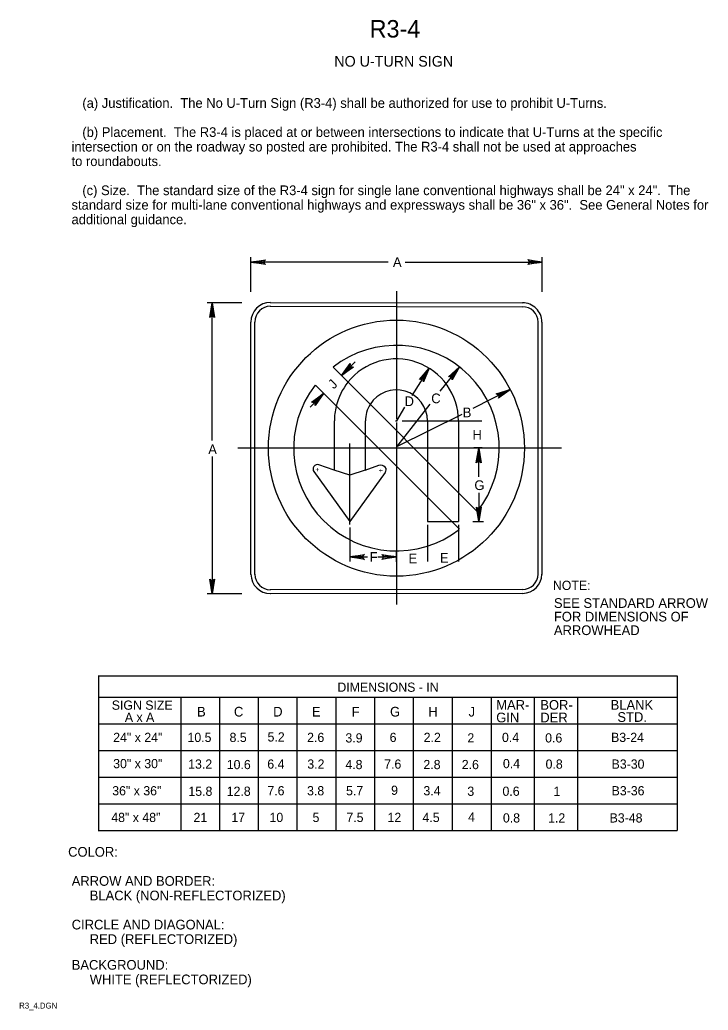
# Model space of a CAD drawing. Extents: x 0.013 to 0.19, y 0.004 to 0.259.
import ezdxf

# ---------------------------------------------------------------- set-up
doc = ezdxf.new("R2010")
doc.units = 0
for name, color, linetype in [('1', 7, 'Continuous'), ('2', 7, 'Continuous'), ('3', 7, 'Continuous')]:
    doc.layers.add(name, color=color, linetype=linetype)

# ---------------------------------------------------------------- blocks, each defined once
blk = doc.blocks.new('RARROW')
at = {"layer": '3'}
for p, q in [((-2.156, 0.28500000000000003), (-2.2665, 0.384625)), ((-2.2665, 0.384625), (0, 0)), ((0, 0), (-2.2665, -0.379125)), ((-2.156, 0.28500000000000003), (-2.075625, 0.12075)), ((0, 0), (-2.156, 0.28500000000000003)), ((-2.14975, -0.2705), (0, 0)), ((-2.075625, 0.12075), (0, 0)), ((0, 0), (-2.074, -0.108)), ((-2.2665, -0.379125), (-2.14975, -0.2705)), ((-2.074, -0.108), (-2.14975, -0.2705))]:
    blk.add_line(p, q, dxfattribs=at)

msp = doc.modelspace()

# ---------------------------------------------------------------- linework, layer by layer
at = {"layer": '1'}
for p, q in [((0.10975, 0.18925), (0.10975, 0.15637500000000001)), ((0.0935, 0.169625), (0.130625, 0.1325)), ((0.088875, 0.165), (0.126, 0.12787500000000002)), ((0.10975, 0.156125), (0.10975, 0.155625)), ((0.11775000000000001, 0.155875), (0.11775000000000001, 0.145375)), ((0.12575, 0.155875), (0.12575, 0.137375)), ((0.10975, 0.155375), (0.10975, 0.1085)), ((0.11775000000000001, 0.145375), (0.11775000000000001, 0.136125)), ((0.11775000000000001, 0.136125), (0.11775000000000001, 0.129875)), ((0.12575, 0.137375), (0.12575, 0.129875))]:
    msp.add_line(p, q, dxfattribs=at)
at = {"layer": '3'}
for p, q in [((0.07225, 0.189090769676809), (0.07225, 0.198)), ((0.107625, 0.19675), (0.07225, 0.19675)), ((0.112, 0.19675), (0.147375, 0.19675)), ((0.147375, 0.189090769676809), (0.147375, 0.198)), ((0.07725, 0.186375), (0.14225000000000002, 0.18625)), ((0.06990747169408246, 0.18625), (0.061, 0.18625)), ((0.06225, 0.15075), (0.06225, 0.18625)), ((0.07725, 0.185375), (0.14225000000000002, 0.18525)), ((0.07225, 0.11625), (0.07225, 0.18125)), ((0.07325, 0.11625), (0.07325, 0.18125)), ((0.14625, 0.18125), (0.14625, 0.11625)), ((0.14725, 0.18125), (0.14725, 0.11625)), ((0.099125, 0.171), (0.095625, 0.1675)), ((0.11825000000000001, 0.169375), (0.11375, 0.162375)), ((0.126, 0.16975), (0.121, 0.1635)), ((0.139125, 0.163875), (0.1295, 0.159)), ((0.08750000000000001, 0.15937500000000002), (0.091, 0.162875)), ((0.11837500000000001, 0.160125), (0.10975, 0.149125)), ((0.111875, 0.15937500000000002), (0.10975, 0.155875)), ((0.09375, 0.155875), (0.09375, 0.143125)), ((0.10175000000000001, 0.155875), (0.10175000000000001, 0.152125)), ((0.1095, 0.155875), (0.11, 0.155875)), ((0.12662500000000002, 0.1575), (0.10975, 0.149125)), ((0.11125, 0.155875), (0.13175, 0.155875)), ((0.10175000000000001, 0.152125), (0.10175000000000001, 0.143125)), ((0.068875, 0.148875), (0.152375, 0.148875)), ((0.09775, 0.129125), (0.09775, 0.15)), ((0.131875, 0.148875), (0.12975, 0.148875)), ((0.131, 0.141375), (0.131, 0.148875)), ((0.131, 0.143875), (0.131, 0.148875)), ((0.06225, 0.146625), (0.06225, 0.11125)), ((0.09375, 0.143125), (0.08975, 0.1445)), ((0.09775, 0.141875), (0.09375, 0.143125)), ((0.10175000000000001, 0.143125), (0.09775, 0.141875)), ((0.10175000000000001, 0.143125), (0.10525, 0.144375)), ((0.0885, 0.14275000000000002), (0.09775, 0.129875)), ((0.106875, 0.14250000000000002), (0.09775, 0.129875)), ((0.106875, 0.14250000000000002), (0.106875, 0.14250000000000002)), ((0.131, 0.13725), (0.131, 0.129875)), ((0.09775, 0.128375), (0.09775, 0.11962500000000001)), ((0.11775000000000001, 0.129875), (0.124, 0.129875)), ((0.11775000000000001, 0.129), (0.11775000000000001, 0.11962500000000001)), ((0.124, 0.129875), (0.12575, 0.129875)), ((0.12575, 0.129), (0.12575, 0.11962500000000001)), ((0.1295, 0.129875), (0.13225, 0.129875)), ((0.09775, 0.12075), (0.1023042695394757, 0.12075)), ((0.105, 0.12075), (0.10975, 0.12075)), ((0.10975, 0.11950000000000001), (0.10975, 0.122125)), ((0.14225000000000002, 0.112375), (0.07725, 0.11225)), ((0.06990747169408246, 0.11125), (0.061, 0.11125)), ((0.14225000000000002, 0.111375), (0.07725, 0.11125)), ((0.032875, 0.090125), (0.182125, 0.090125)), ((0.032916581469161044, 0.09012213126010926), (0.032916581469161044, 0.050247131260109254)), ((0.18216658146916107, 0.09012213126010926), (0.18216658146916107, 0.050247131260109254)), ((0.182125, 0.0845), (0.032875, 0.0845)), ((0.05416658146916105, 0.08449713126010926), (0.05416658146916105, 0.050247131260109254)), ((0.064125, 0.0845), (0.064125, 0.05025)), ((0.074125, 0.0845), (0.074125, 0.05025)), ((0.084125, 0.0845), (0.084125, 0.05025)), ((0.094125, 0.0845), (0.094125, 0.05025)), ((0.104125, 0.0845), (0.104125, 0.05025)), ((0.114125, 0.0845), (0.114125, 0.05025)), ((0.124125, 0.0845), (0.124125, 0.05025)), ((0.13416658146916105, 0.08449713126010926), (0.13416658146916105, 0.050247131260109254)), ((0.13416658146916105, 0.08449713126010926), (0.13416658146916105, 0.050247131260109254)), ((0.14529158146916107, 0.08449713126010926), (0.14529158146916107, 0.050247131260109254)), ((0.15641658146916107, 0.08449713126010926), (0.15641658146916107, 0.050247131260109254)), ((0.032875, 0.07775), (0.182125, 0.07775)), ((0.032875, 0.07087500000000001), (0.182125, 0.07087500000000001)), ((0.032875, 0.064), (0.182125, 0.064)), ((0.032875, 0.057125), (0.182125, 0.057125)), ((0.032875, 0.05025), (0.182125, 0.05025))]:
    msp.add_line(p, q, dxfattribs=at)
msp.add_circle((0.10977464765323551, 0.14880006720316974), 0.033, dxfattribs=at)
for centre, radius, start, end in [((0.07733185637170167, 0.18129027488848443), 0.005082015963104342, 90.45407222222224, 180.45407222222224), ((0.07731914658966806, 0.18132763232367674), 0.004044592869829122, 90.39049166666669, 180.3904916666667), ((0.1423095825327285, 0.1812820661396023), 0.004965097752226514, 0.20772777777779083, 90.20772777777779), ((0.1423095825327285, 0.1812820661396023), 0.0039651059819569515, 0.26011666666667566, 90.26011666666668), ((0.10977464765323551, 0.14880006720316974), 0.0265, 321.8964166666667, 128.1035833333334), ((0.10977464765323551, 0.15580006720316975), 0.016, 0, 141.3433), ((0.10977464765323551, 0.14880006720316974), 0.0265, 142.28156944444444, 307.7184305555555), ((0.10977464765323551, 0.15580006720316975), 0.016, 141.3433, 166.28407222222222), ((0.10977464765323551, 0.15580006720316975), 0.008, 0, 147.7660638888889), ((0.10977464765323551, 0.15580006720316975), 0.016, 166.28407222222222, 180), ((0.10977464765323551, 0.15580006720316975), 0.008, 147.7660638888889, 180.00000000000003), ((0.08940938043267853, 0.14342187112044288), 0.001130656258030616, 72.46680555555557, 216.45783888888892), ((0.07727464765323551, 0.11630006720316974), 0.005, 180, 270), ((0.07727464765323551, 0.11630006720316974), 0.004, 180, 270), ((0.14231914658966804, 0.11632763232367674), 0.003955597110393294, 269.6007222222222, 359.6007222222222), ((0.14231914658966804, 0.11632763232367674), 0.004955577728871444, 269.68129444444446, 359.68129444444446)]:
    msp.add_arc(centre, radius, start, end, dxfattribs=at)
msp.add_ellipse((0.10566315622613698, 0.14320738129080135), major_axis=(-0.0014907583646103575, 1.8256524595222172e-19), ratio=0.8090695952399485, start_param=2.5023576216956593, end_param=5.015591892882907, dxfattribs=at)

# ---------------------------------------------------------------- block references
for p, xscale, yscale, rotation in [((0.07225, 0.19675), 0.0016545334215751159, 0.0016366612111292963, 180), ((0.06225, 0.18625), 0.0016545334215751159, 0.0016366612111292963, 90), ((0.095625, 0.1675), 0.001654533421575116, 0.001636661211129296, -135), ((0.11825000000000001, 0.169375), 0.0016545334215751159, 0.0016366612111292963, 58.04189052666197), ((0.126, 0.16975), 0.0016545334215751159, 0.0016366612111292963, 51.811927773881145), ((0.139125, 0.163875), 0.0016545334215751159, 0.0016366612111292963, 26.565051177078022), ((0.091, 0.162875), 0.001654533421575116, 0.001636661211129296, 45), ((0.131, 0.14875), 0.0016545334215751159, 0.0016366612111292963, 90), ((0.131, 0.129875), 0.0016545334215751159, 0.0016366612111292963, -90), ((0.09775, 0.12075), 0.0016545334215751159, 0.0016366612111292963, 180), ((0.06225, 0.11125), 0.0016545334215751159, 0.0016366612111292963, -90)]:
    msp.add_blockref('RARROW', p, dxfattribs=dict(at, xscale=xscale, yscale=yscale, rotation=rotation))
at = {"layer": '3', "xscale": 0.0016545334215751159, "yscale": 0.0016366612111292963}
for p in [(0.147375, 0.19675), (0.10975, 0.12075)]:
    msp.add_blockref('RARROW', p, dxfattribs=at)

# ---------------------------------------------------------------- texts
at = {"layer": '1'}
for s, height, p in [('R3-4', 0.0045000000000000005, (0.10287500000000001, 0.254625)), ('NO U-TURN SIGN', 0.00275025, (0.09375, 0.247125)), ('NOTE:', 0.0023752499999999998, (0.150125, 0.11225)), ('SEE STANDARD ARROW', 0.0024997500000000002, (0.150375, 0.107625)), ('FOR DIMENSIONS OF', 0.0024997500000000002, (0.150375, 0.104125)), ('ARROWHEAD', 0.0024997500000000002, (0.150375, 0.100625)), ('COLOR:', 0.0024997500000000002, (0.025125, 0.043500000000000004)), (' ARROW AND BORDER:', 0.0024997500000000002, (0.025125, 0.036000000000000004)), ('      BLACK (NON-REFLECTORIZED)', 0.0024997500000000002, (0.025125, 0.03225)), (' CIRCLE AND DIAGONAL:', 0.0024997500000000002, (0.025125, 0.02475)), ('      RED (REFLECTORIZED)', 0.0024997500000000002, (0.025125, 0.021)), (' BACKGROUND:', 0.0024997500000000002, (0.025125, 0.014375)), ('      WHITE (REFLECTORIZED)', 0.0024997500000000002, (0.025125, 0.010625)), ('R3_4.DGN', 0.0015, (0.0125, 0.004375))]:
    msp.add_text(s, height=height, dxfattribs=at).set_placement(p)
at = {"layer": '2'}
for s, p in [('   (a) Justification.  The No U-Turn Sign (R3-4) shall be authorized for use to prohibit U-Turns.', (0.026000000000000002, 0.23650025)), ('   (b) Placement.  The R3-4 is placed at or between intersections to indicate that U-Turns at the specific ', (0.026000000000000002, 0.22900075)), ('intersection or on the roadway so posted are prohibited. The R3-4 shall not be used at approaches ', (0.026000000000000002, 0.225251)), ('to roundabouts.', (0.026000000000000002, 0.22150125)), ('   (c) Size.  The standard size of the R3-4 sign for single lane conventional highways shall be 24" x 24".  The ', (0.026000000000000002, 0.21400175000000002)), ('standard size for multi-lane conventional highways and expressways shall be 36" x 36".  See General Notes for ', (0.026000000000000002, 0.21025200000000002)), ('additional guidance.', (0.026000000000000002, 0.20650225))]:
    msp.add_text(s, height=0.0024997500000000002, dxfattribs=at).set_placement(p)
at = {"layer": '3'}
for s, height, p in [('A', 0.0024997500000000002, (0.108875, 0.1955)), ('D', 0.0024997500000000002, (0.111875, 0.15962500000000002)), ('C', 0.0024997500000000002, (0.11875000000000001, 0.160375)), ('B', 0.0024997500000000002, (0.12687500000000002, 0.15675)), ('H', 0.0024997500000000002, (0.129375, 0.151)), ('A', 0.0024997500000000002, (0.06125, 0.14725)), ('G', 0.0024997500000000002, (0.129875, 0.138)), ('F', 0.0024997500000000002, (0.10287500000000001, 0.11950000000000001)), ('E', 0.0024997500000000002, (0.112875, 0.11912500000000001)), ('E', 0.0024997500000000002, (0.121, 0.11925000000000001)), ('DIMENSIONS - IN', 0.0023752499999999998, (0.09454229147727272, 0.08600000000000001)), ('SIGN SIZE', 0.0023752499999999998, (0.036375, 0.081375)), ('B', 0.0024997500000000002, (0.058375, 0.079625)), ('C', 0.0024997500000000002, (0.067875, 0.079625)), ('D', 0.0024997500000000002, (0.078, 0.079625)), ('E', 0.0024997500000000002, (0.088, 0.079625)), ('F', 0.0024997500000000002, (0.09825, 0.079625)), ('G', 0.0024997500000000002, (0.108125, 0.079625)), ('H', 0.0024997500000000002, (0.11800000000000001, 0.079625)), ('J', 0.0024997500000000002, (0.128375, 0.079625)), ('MAR-', 0.0024997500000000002, (0.1355, 0.081375)), ('BOR-', 0.0024997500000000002, (0.146875, 0.081375)), ('BLANK', 0.0024997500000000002, (0.165, 0.081375)), ('A x A', 0.0023752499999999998, (0.03975, 0.07825)), ('GIN', 0.0024997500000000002, (0.1355, 0.078125)), ('DER', 0.0024997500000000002, (0.146875, 0.078125)), ('STD.', 0.0024997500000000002, (0.16675, 0.07825)), ('24" x 24"', 0.0023752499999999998, (0.03674541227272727, 0.073062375)), ('10.5', 0.0023752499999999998, (0.055901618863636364, 0.073062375)), ('8.5', 0.0023752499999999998, (0.0667463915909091, 0.073062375)), ('5.2', 0.0023752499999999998, (0.07654497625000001, 0.073187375)), ('2.6', 0.0023752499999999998, (0.0867435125, 0.073062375)), ('3.9', 0.0023752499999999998, (0.09662211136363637, 0.072937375)), ('6', 0.0023752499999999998, (0.10802206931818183, 0.073062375)), ('2.2', 0.0023752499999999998, (0.11679497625, 0.073062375)), ('2', 0.0023752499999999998, (0.12807353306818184, 0.072937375)), ('0.4', 0.0023752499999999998, (0.13698199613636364, 0.073062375)), ('0.6', 0.0023752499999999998, (0.14811851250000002, 0.072937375)), ('B3-24', 0.0023752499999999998, (0.1651149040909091, 0.073062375)), ('30" x 30"', 0.0023752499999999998, (0.03674541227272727, 0.066312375)), ('13.2', 0.0023752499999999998, (0.056075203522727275, 0.066187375)), ('10.6', 0.0023752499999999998, (0.06602373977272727, 0.066062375)), ('6.4', 0.0023752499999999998, (0.07648199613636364, 0.066187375)), ('3.2', 0.0023752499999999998, (0.08679497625, 0.066187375)), ('4.8', 0.0023752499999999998, (0.0966055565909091, 0.066062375)), ('7.6', 0.0023752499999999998, (0.1066185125, 0.066187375)), ('2.8', 0.0023752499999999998, (0.11673055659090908, 0.066062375)), ('2.6', 0.0023752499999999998, (0.1266185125, 0.066062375)), ('0.4', 0.0023752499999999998, (0.13723199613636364, 0.066312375)), ('0.8', 0.0023752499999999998, (0.14823055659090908, 0.066187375)), ('B3-30', 0.0023752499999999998, (0.16524638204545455, 0.066187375)), ('36" x 36"', 0.0023752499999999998, (0.03649541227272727, 0.05931237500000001)), ('15.8', 0.0023752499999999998, (0.056135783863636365, 0.05918737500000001)), ('12.8', 0.0023752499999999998, (0.06601078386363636, 0.05918737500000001)), ('7.6', 0.0023752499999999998, (0.0764935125, 0.05931237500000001)), ('3.8', 0.0023752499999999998, (0.08673055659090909, 0.05931237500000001)), ('5.7', 0.0023752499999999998, (0.09677914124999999, 0.05931237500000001)), ('9', 0.0023752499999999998, (0.10840066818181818, 0.05943737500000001)), ('3.4', 0.0023752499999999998, (0.11673199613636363, 0.05931237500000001)), ('3', 0.0023752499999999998, (0.1280566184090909, 0.05918737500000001)), ('0.6', 0.0023752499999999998, (0.1371185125, 0.05918737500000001)), ('1', 0.0023752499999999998, (0.15026895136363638, 0.05918737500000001)), ('B3-36', 0.0023752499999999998, (0.16525142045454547, 0.05931237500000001)), ('48" x 48"', 0.0023752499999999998, (0.036245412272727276, 0.052437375)), ('21', 0.0023752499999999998, (0.05745824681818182, 0.052437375)), ('17', 0.0023752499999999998, (0.0672129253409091, 0.052437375)), ('10', 0.0023752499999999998, (0.07704725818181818, 0.052437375)), ('5', 0.0023752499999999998, (0.0881499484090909, 0.052437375)), ('7.5', 0.0023752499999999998, (0.0968713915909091, 0.052437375)), ('12', 0.0023752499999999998, (0.1074787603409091, 0.052437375)), ('4.5', 0.0023752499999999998, (0.1164963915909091, 0.052437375)), ('4', 0.0023752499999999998, (0.12826055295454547, 0.052562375)), ('0.8', 0.0023752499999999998, (0.1372305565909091, 0.052312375)), ('1.2', 0.0023752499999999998, (0.1488859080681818, 0.052312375)), ('B3-48', 0.0023752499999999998, (0.16473846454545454, 0.052312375))]:
    msp.add_text(s, height=height, dxfattribs=at).set_placement(p)
for s, height, rotation, p in [('J', 0.0024997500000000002, 45, (0.093625, 0.163875)), ('+', 0.00130575, 270, (0.08875, 0.14375000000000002)), ('+', 0.00130575, 270, (0.105125, 0.14350000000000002))]:
    msp.add_text(s, height=height, rotation=rotation, dxfattribs=at).set_placement(p)

doc.saveas('drawing.dxf')
